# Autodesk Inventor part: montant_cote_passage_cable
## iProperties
Created: 2011-01
Part Number: montant_cote_passage_cable
Document SubType Name: Modeling
Designer: eric
Density: 1 g/cm^3
Mass: 31.0824 g
Surface Area: 328.599 cm^2
Volume: 31.0824 cm^3
Author: eric
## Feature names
1. Base1
